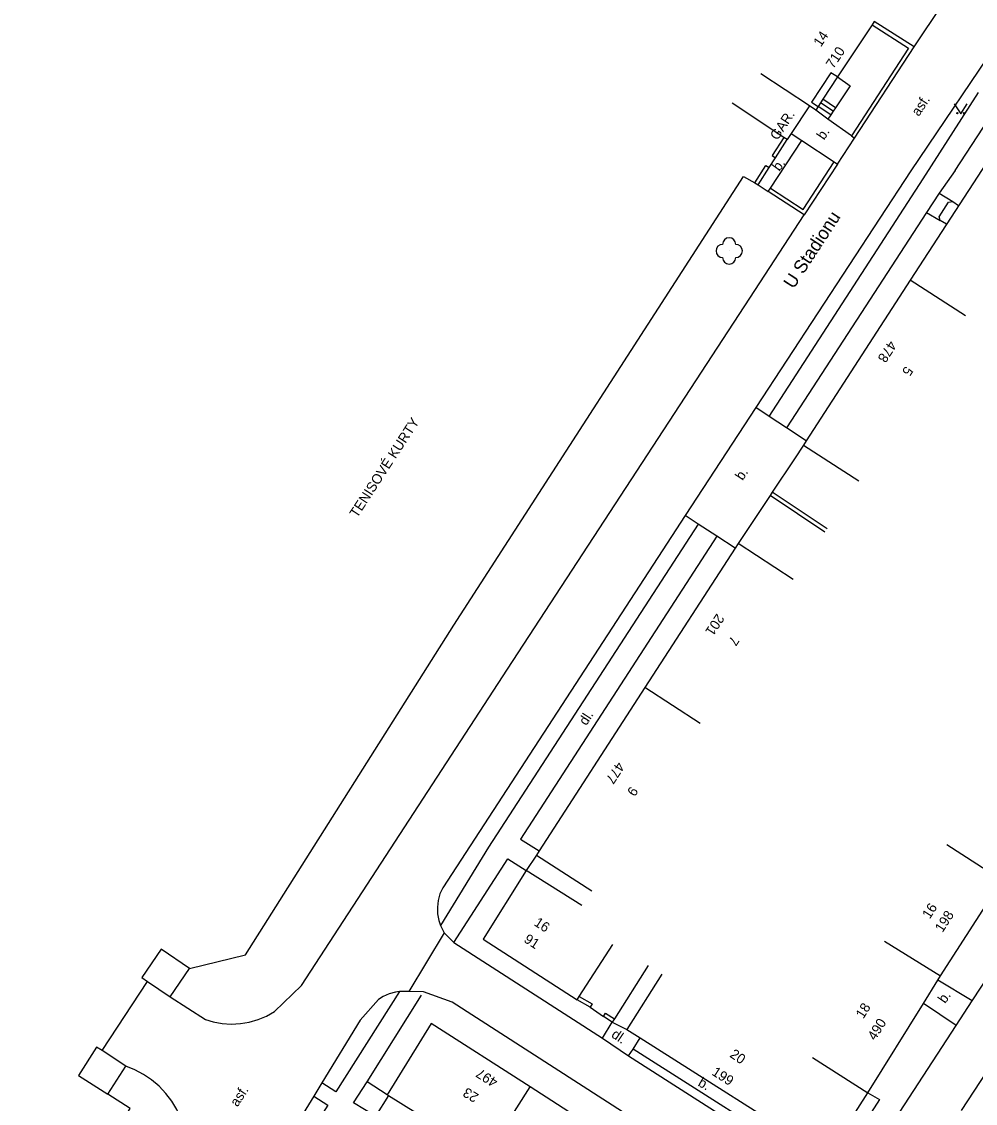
# Model space of a CAD drawing. Extents: x -577457 to -568404, y -1208466 to -1201387.
# Drawn here: x -568988.4 to -568916, y -1204114.1 to -1204031.9 of the extents above; entities that cross this region are included whole.
import ezdxf

# ---------------------------------------------------------------- set-up
doc = ezdxf.new("R2010")
doc.units = 0
for name, color, linetype in [('BUDOVY_MĚŘ', 7, 'Continuous'), ('NÁZVY_ULIC_TOK_SMĚR', 7, 'Continuous'), ('POMOC_POPIS', 7, 'Continuous'), ('ROZHRANÍ_PLOCH', 7, 'Continuous'), ('ZELEŇ', 7, 'Continuous'), ('ZN_DOPLŇKOVÉ', 7, 'Continuous'), ('ZN_KULTUR', 7, 'Continuous'), ('Č_POPIS_ORIENT', 7, 'Continuous')]:
    doc.layers.add(name, color=color, linetype=linetype)

msp = doc.modelspace()

# ---------------------------------------------------------------- linework, layer by layer
at = {"layer": 'BUDOVY_MĚŘ'}
for points in [[(-568923.83, -1204032.15), (-568926.45, -1204036.12)], [(-568923.66, -1204031.9), (-568923.83, -1204032.15)], [(-568928.59, -1204038.31), (-568932.28, -1204035.87)], [(-568926.45, -1204036.12), (-568926.96, -1204035.8), (-568928.43, -1204038.03), (-568927.93, -1204038.36)], [(-568926.45, -1204036.12), (-568927.56, -1204037.8)], [(-568927.56, -1204037.8), (-568927.75, -1204038.08)], [(-568930.53, -1204040.71), (-568934.45, -1204038.11)], [(-568928.59, -1204038.31), (-568929.98, -1204040.41)], [(-568928.11, -1204038.63), (-568928.59, -1204038.31)], [(-568927.93, -1204038.36), (-568928.11, -1204038.63)], [(-568927.75, -1204038.08), (-568927.93, -1204038.36)], [(-568929.98, -1204040.41), (-568930.28, -1204040.87)], [(-568930.28, -1204040.87), (-568930.53, -1204040.71)], [(-568913.78, -1204040.55), (-568920.94, -1204051.55)], [(-568920.94, -1204051.55), (-568928.83, -1204063.74)], [(-568916.74, -1204054.27), (-568920.94, -1204051.55)], [(-568928.83, -1204063.74), (-568929.04, -1204064.07)], [(-568929.04, -1204064.07), (-568924.84, -1204066.79)], [(-568934, -1204071.56), (-568934.22, -1204071.9)], [(-568929.81, -1204074.28), (-568934, -1204071.56)], [(-568934.22, -1204071.9), (-568941.09, -1204082.49)], [(-568941.09, -1204082.49), (-568949.12, -1204094.9)], [(-568936.89, -1204085.21), (-568941.09, -1204082.49)], [(-568918.15, -1204094.4), (-568913.95, -1204097.11)], [(-568949.12, -1204094.9), (-568949.32, -1204095.21)], [(-568949.32, -1204095.21), (-568945.12, -1204097.93)], [(-568950.09, -1204096.37), (-568953.37, -1204101.59), (-568946.23, -1204106.21)], [(-568945.86, -1204099.03), (-568950.09, -1204096.37)], [(-568918.63, -1204104.38), (-568913.95, -1204097.11)], [(-568946.07, -1204105.96), (-568943.51, -1204102.01)], [(-568922.88, -1204101.75), (-568918.63, -1204104.38)], [(-568975.66, -1204103.83), (-568977.81, -1204102.36), (-568979.28, -1204104.51), (-568978.86, -1204104.8)], [(-568977.13, -1204105.98), (-568975.66, -1204103.83)], [(-568939.79, -1204104.26), (-568942.45, -1204108.45)], [(-568918.83, -1204104.7), (-568918.63, -1204104.38)], [(-568978.86, -1204104.8), (-568977.13, -1204105.98)], [(-568919.93, -1204106.48), (-568918.83, -1204104.7)], [(-568946.23, -1204106.21), (-568946.07, -1204105.96)], [(-568924.14, -1204113.27), (-568919.93, -1204106.48)], [(-568949.79, -1204112.82), (-568957.31, -1204108.01), (-568960.65, -1204113.41)], [(-568942.45, -1204108.45), (-568941.43, -1204109.1)], [(-568941.43, -1204109.1), (-568927.25, -1204118.11), (-568924.14, -1204113.27)], [(-568982.3, -1204110.06), (-568982.72, -1204109.79), (-568984.1, -1204111.94), (-568981.87, -1204113.37)], [(-568980.5, -1204111.24), (-568982.3, -1204110.06)], [(-568928.35, -1204110.57), (-568924.14, -1204113.27)], [(-568981.87, -1204113.37), (-568980.5, -1204111.24)], [(-568981.52, -1204116.57), (-568980.17, -1204114.46), (-568981.87, -1204113.37)], [(-568960.56, -1204113.47), (-568961.53, -1204115.03)], [(-568960.65, -1204113.41), (-568960.56, -1204113.47)], [(-568960.56, -1204113.47), (-568956.4, -1204116.04)], [(-568952.48, -1204117.03), (-568949.79, -1204112.82)], [(-568945.63, -1204115.5), (-568949.79, -1204112.82)]]:
    msp.add_lwpolyline(points, dxfattribs=at)
at = {"layer": 'ROZHRANÍ_PLOCH'}
for points in [[(-568920.63, -1204033.84), (-568916.27, -1204027.29)], [(-568913.77, -1204032.71), (-568920.89, -1204043.24)], [(-568926.45, -1204036.12), (-568925.5, -1204036.78), (-568926.6, -1204038.45)], [(-568926.6, -1204038.45), (-568927.56, -1204037.8)], [(-568919.95, -1204043.86), (-568915.74, -1204037.31)], [(-568927.18, -1204039.33), (-568928.11, -1204038.63)], [(-568926.96, -1204039), (-568927.93, -1204038.36)], [(-568926.78, -1204038.72), (-568927.75, -1204038.08)], [(-568926.78, -1204038.72), (-568926.96, -1204039)], [(-568926.6, -1204038.45), (-568926.78, -1204038.72)], [(-568926.96, -1204039), (-568927.18, -1204039.33)], [(-568925.39, -1204040.6), (-568927.18, -1204039.33)], [(-568917.53, -1204043.23), (-568914.98, -1204039.34)], [(-568929.98, -1204040.41), (-568929.16, -1204040.95)], [(-568931.55, -1204044.57), (-568929.16, -1204040.95)], [(-568929.16, -1204040.95), (-568926.71, -1204042.57)], [(-568926.46, -1204042.74), (-568925.16, -1204040.76)], [(-568920.89, -1204043.24), (-568932.65, -1204061.21)], [(-568917.53, -1204043.23), (-568918.74, -1204044.94), (-568919.69, -1204046.4), (-568930.33, -1204062.77)], [(-568932.48, -1204044.31), (-568931.71, -1204044.82)], [(-568931.71, -1204044.82), (-568931.55, -1204044.57)], [(-568931.64, -1204061.91), (-568919.95, -1204043.86)], [(-568977.13, -1204105.98), (-568974.46, -1204107.69), (-568973.87, -1204107.87), (-568973.19, -1204107.99), (-568972.5, -1204108.04), (-568971.8, -1204108.01), (-568971.12, -1204107.89), (-568970.45, -1204107.7), (-568969.81, -1204107.44), (-568969.2, -1204107.1), (-568967.17, -1204105.12), (-568951.52, -1204081.09), (-568933.12, -1204052.92), (-568928.99, -1204046.6)], [(-568916.23, -1204106.27), (-568916.18, -1204106.2), (-568898.77, -1204079.68), (-568885.27, -1204059.03)], [(-568932.65, -1204061.21), (-568938.02, -1204069.43)], [(-568931.64, -1204061.91), (-568932.65, -1204061.21)], [(-568930.33, -1204062.77), (-568931.64, -1204061.91)], [(-568928.83, -1204063.74), (-568930.33, -1204062.77)], [(-568938.02, -1204069.43), (-568956.42, -1204097.69), (-568956.64, -1204098.16), (-568956.78, -1204098.65), (-568956.84, -1204099.17), (-568956.83, -1204099.68), (-568956.73, -1204100.19), (-568956.6, -1204100.57)], [(-568937.04, -1204070.07), (-568952.95, -1204094.6), (-568956.6, -1204100.57)], [(-568937.04, -1204070.07), (-568938.02, -1204069.43)], [(-568935.61, -1204070.99), (-568937.04, -1204070.07)], [(-568935.61, -1204070.99), (-568950.53, -1204093.99), (-568949.12, -1204094.9)], [(-568934.22, -1204071.9), (-568935.61, -1204070.99)], [(-568955.58, -1204101.84), (-568951.48, -1204095.49), (-568950.09, -1204096.37)], [(-568956.32, -1204101.12), (-568959, -1204105.58)], [(-568956.6, -1204100.57), (-568956.56, -1204100.67), (-568956.32, -1204101.12)], [(-568956.32, -1204101.12), (-568955.58, -1204101.84)], [(-568955.58, -1204101.84), (-568944.31, -1204109.12)], [(-568909.84, -1204103.59), (-568917.07, -1204114.62)], [(-568916.23, -1204106.27), (-568918.83, -1204104.7)], [(-568959.72, -1204105.58), (-568964.54, -1204113.19), (-568965.62, -1204112.51)], [(-568959.72, -1204105.58), (-568960.01, -1204105.61), (-568960.5, -1204105.75), (-568960.96, -1204105.95), (-568961.31, -1204106.18), (-568962.7, -1204107.75), (-568965.62, -1204112.51)], [(-568959, -1204105.58), (-568959.51, -1204105.56), (-568959.72, -1204105.58)], [(-568930.19, -1204122.8), (-568944.27, -1204113.75), (-568955.71, -1204106.38), (-568957.89, -1204105.59), (-568959, -1204105.58)], [(-568917.45, -1204108.16), (-568919.93, -1204106.48)], [(-568917.45, -1204108.16), (-568916.23, -1204106.27)], [(-568944.31, -1204109.12), (-568943.56, -1204107.91)], [(-568942.32, -1204110.46), (-568928.08, -1204119.56), (-568927.64, -1204119.77), (-568927.18, -1204119.9), (-568926.7, -1204119.95), (-568926.22, -1204119.93), (-568926.11, -1204119.91), (-568925.59, -1204119.73), (-568925.09, -1204119.48), (-568924.64, -1204119.15), (-568924.59, -1204119.11), (-568917.45, -1204108.16)], [(-568944.31, -1204109.12), (-568942.32, -1204110.46)], [(-568941.98, -1204109.94), (-568941.43, -1204109.1)], [(-568942.32, -1204110.46), (-568941.98, -1204109.94)], [(-568924.14, -1204113.27), (-568923.26, -1204113.77), (-568926.42, -1204118.7), (-568926.57, -1204118.94), (-568926.77, -1204119.1), (-568927.01, -1204119.19), (-568927.27, -1204119.2), (-568927.51, -1204119.14), (-568927.73, -1204119), (-568941.98, -1204109.94)], [(-568988.41, -1204138.33), (-568976.89, -1204120.11), (-568975.82, -1204117.25), (-568975.9, -1204116.65), (-568976.06, -1204115.92), (-568976.3, -1204115.22), (-568976.62, -1204114.54), (-568977, -1204113.9), (-568977.45, -1204113.31), (-568977.97, -1204112.77), (-568978.54, -1204112.29), (-568979.15, -1204111.87), (-568979.81, -1204111.52), (-568980.5, -1204111.24)], [(-568965.62, -1204112.51), (-568966.23, -1204113.51)], [(-568961.53, -1204115.03), (-568963.22, -1204114.03), (-568962.17, -1204112.42)], [(-568966.23, -1204113.51), (-568978.84, -1204134.05)], [(-568966.23, -1204113.51), (-568965.17, -1204114.2), (-568970.08, -1204121.94)]]:
    msp.add_lwpolyline(points, dxfattribs=at)
at = {"layer": 'ZELEŇ'}
msp.add_circle((-568934.68, -1204049.33), 0.0005, dxfattribs=at)
for centre, start, end in [((-568934.68, -1204048.83), 0, 179.99999), ((-568935.18, -1204049.33), 89.99999, 269.99999), ((-568934.18, -1204049.33), 270, 89.99999), ((-568934.68, -1204049.83), 179.99999, 359.99999)]:
    msp.add_arc(centre, 0.5, start, end, dxfattribs=at)
at = {"layer": 'ZN_DOPLŇKOVÉ'}
for points in [[(-568923.83, -1204032.15), (-568921.05, -1204033.93), (-568925.39, -1204040.6)], [(-568920.63, -1204033.84), (-568923.66, -1204031.9)], [(-568925.16, -1204040.76), (-568920.63, -1204033.84)], [(-568930.53, -1204040.71), (-568931.41, -1204042.09), (-568931.16, -1204042.25)], [(-568931.16, -1204042.25), (-568930.28, -1204040.87)], [(-568925.39, -1204040.6), (-568925.16, -1204040.76)], [(-568932.74, -1204044.16), (-568931.89, -1204042.83), (-568931.64, -1204042.99)], [(-568931.64, -1204042.99), (-568931.16, -1204042.25)], [(-568931.55, -1204044.57), (-568929.07, -1204046.19), (-568926.71, -1204042.57)], [(-568926.46, -1204042.74), (-568928.99, -1204046.6)], [(-568926.71, -1204042.57), (-568926.46, -1204042.74)], [(-568975.66, -1204103.83), (-568971.42, -1204102.79), (-568955.59, -1204077.74), (-568933.58, -1204043.68), (-568932.74, -1204044.16)], [(-568932.48, -1204044.31), (-568931.64, -1204042.99)], [(-568932.74, -1204044.16), (-568932.48, -1204044.31)], [(-568928.99, -1204046.6), (-568931.71, -1204044.82)], [(-568918.74, -1204044.94), (-568917.7, -1204045.58)], [(-568918.18, -1204047.3), (-568918.65, -1204047.03), (-568918.73, -1204046.74), (-568918.02, -1204045.62), (-568917.7, -1204045.58), (-568917.26, -1204045.89)], [(-568919.69, -1204046.4), (-568918.65, -1204047.03)], [(-568929.04, -1204064.07), (-568929.73, -1204065.11), (-568931.41, -1204067.66)], [(-568931.57, -1204067.91), (-568933.44, -1204070.72), (-568934, -1204071.56)], [(-568931.41, -1204067.66), (-568931.57, -1204067.91)], [(-568927.41, -1204070.68), (-568931.57, -1204067.91)], [(-568927.24, -1204070.43), (-568931.41, -1204067.66)], [(-568949.32, -1204095.21), (-568950.09, -1204096.37)], [(-568940.82, -1204103.6), (-568943.4, -1204107.65)], [(-568982.3, -1204110.06), (-568978.86, -1204104.8)], [(-568962.17, -1204112.42), (-568958.04, -1204105.86)], [(-568945.24, -1204106.77), (-568946.23, -1204106.21)], [(-568946.07, -1204105.96), (-568945.09, -1204106.51), (-568945.24, -1204106.77)], [(-568945.24, -1204106.77), (-568944.23, -1204107.46)], [(-568944.23, -1204107.46), (-568944.06, -1204107.21), (-568943.4, -1204107.65)], [(-568943.56, -1204107.91), (-568944.23, -1204107.46)], [(-568943.4, -1204107.65), (-568943.56, -1204107.91)], [(-568943.56, -1204107.91), (-568942.45, -1204108.45)], [(-568960.65, -1204113.41), (-568962.17, -1204112.42)]]:
    msp.add_lwpolyline(points, dxfattribs=at)
at = {"layer": 'ZN_KULTUR'}
msp.add_lwpolyline([(-568917.6, -1204038.17), (-568917.1, -1204038.92), (-568916.6, -1204038.17)], dxfattribs=at)
for centre in [(-568917.35, -1204038.87), (-568916.85, -1204038.87)]:
    msp.add_circle(centre, 0.05, dxfattribs=at)

# ---------------------------------------------------------------- texts
at = {"layer": 'NÁZVY_ULIC_TOK_SMĚR'}
msp.add_text('U Stadionu', height=1, rotation=56.85002, dxfattribs=at).set_placement((-568929.79, -1204052.27))
at = {"layer": 'POMOC_POPIS'}
for s, rotation, p in [('asf.', 56.59998, (-568920.28, -1204039.16)), ('GAR.', 56.51999, (-568931.01, -1204040.98)), ('b.', 55.84001, (-568927.48, -1204040.95)), ('b.', 53.59, (-568930.87, -1204043.33)), ('TENISOVÉ KURTY', 57.04998, (-568962.93, -1204069.65)), ('b.', 56.83999, (-568933.66, -1204066.81)), ('dl.', 57.02998, (-568945.53, -1204085.42)), ('b.', 55.39001, (-568918.28, -1204106.53)), ('dl.', 326.03997, (-568943.69, -1204108.99)), ('b.', 330.61, (-568937.11, -1204112.7)), ('asf.', 56.87001, (-568972.02, -1204114.38))]:
    msp.add_text(s, height=0.75, rotation=rotation, dxfattribs=at).set_placement(p)
at = {"layer": 'Č_POPIS_ORIENT'}
for s, rotation, p in [('14', 56.53002, (-568927.72, -1204033.89)), ('710', 56.53002, (-568926.77, -1204035.54)), ('478', 237.10002, (-568922.53, -1204056.08)), ('5', 237.10002, (-568921.29, -1204058.03)), ('201', 237.03, (-568935.62, -1204076.82)), ('7', 237.10002, (-568934.49, -1204078.52)), ('477', 237.10002, (-568943.19, -1204088.07)), ('9', 237.10002, (-568942.17, -1204089.94)), ('16', 57.23, (-568919.45, -1204100.11)), ('198', 57.23, (-568918.48, -1204101.14)), ('16', 327.08997, (-568949.56, -1204100.51)), ('91', 327.08997, (-568950.33, -1204101.77)), ('18', 58.20999, (-568924.49, -1204107.69)), ('490', 58.20999, (-568923.59, -1204109.34)), ('20', 325.69001, (-568934.69, -1204110.5)), ('497', 147.39998, (-568952.18, -1204112.27)), ('199', 327.55997, (-568936.06, -1204111.86)), ('23', 148.70002, (-568953.64, -1204113.41))]:
    msp.add_text(s, height=0.75, rotation=rotation, dxfattribs=at).set_placement(p)

doc.saveas('drawing.dxf')
